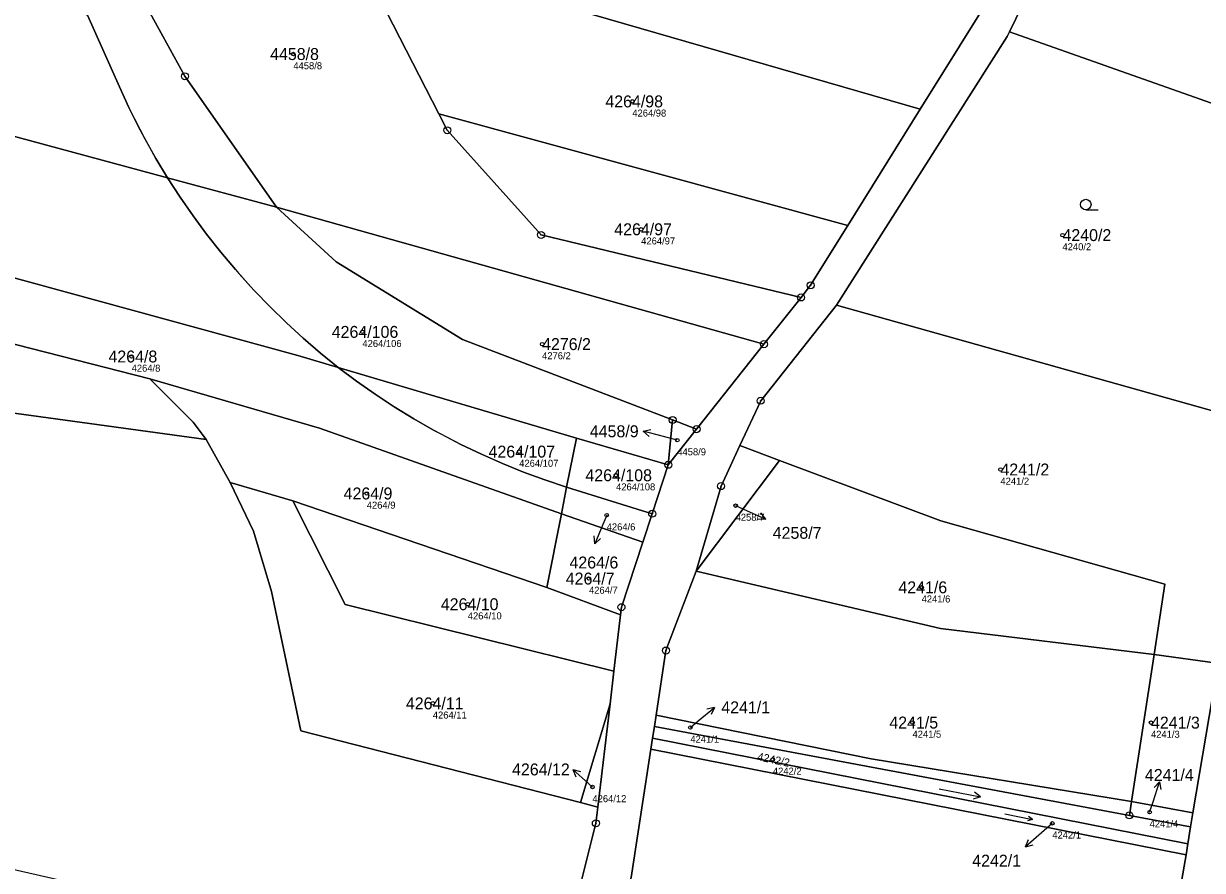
# Model space of a CAD drawing. Extents: x -739214 to -733252, y -1147612 to -1142842.
# Drawn here: x -736907.7 to -736739.7, y -1146244.9 to -1146124.1 of the extents above; entities that cross this region are included whole.
import ezdxf

# ---------------------------------------------------------------- set-up
doc = ezdxf.new("R2010")
doc.units = 0
for name, color, linetype in [('Definiční body', 7, 'Continuous'), ('Hranice parcel', 7, 'Continuous'), ('Parcelní čísla', 7, 'Continuous'), ('Polygon parcely', 7, 'Continuous'), ('Pop  PČ popisy', 7, 'Continuous'), ('Značky bodu BP', 7, 'Continuous'), ('Značky kultur', 7, 'Continuous')]:
    doc.layers.add(name, color=color, linetype=linetype)

msp = doc.modelspace()

# ---------------------------------------------------------------- linework, layer by layer
at = {"layer": 'Definiční body'}
for centre in [(-736869.24, -1146128.5), (-736820.95, -1146135.25), (-736819.68, -1146153.48), (-736759.66, -1146154.31), (-736859.4, -1146168.11), (-736833.8, -1146169.85), (-736892.28, -1146171.62), (-736814.54, -1146183.55), (-736837.06, -1146185.18), (-736823.26, -1146188.55), (-736768.5, -1146187.73), (-736858.78, -1146191.15), (-736824.6, -1146194.25), (-736806.23, -1146192.88), (-736827.12, -1146203.28), (-736779.73, -1146204.53), (-736844.39, -1146206.94), (-736849.37, -1146221.08), (-736781.03, -1146223.81), (-736747.05, -1146223.82), (-736812.68, -1146224.52), (-736800.92, -1146229.07), (-736826.63, -1146233), (-736747.25, -1146236.58), (-736761.11, -1146238.18)]:
    msp.add_circle(centre, 0.25, dxfattribs=at)
at = {"layer": 'Hranice parcel'}
for p, q in [((-736768.72, -1146118.36), (-736779.92, -1146136.37)), ((-736894.03, -1146133.17), (-736898.55, -1146122.95)), ((-736767.21, -1146125.35), (-736726.44, -1146139.74)), ((-736884.69, -1146131.66), (-736871.63, -1146150.35)), ((-736929.53, -1146134.68), (-736887.15, -1146146.15)), ((-736779.92, -1146136.37), (-736790.23, -1146152.94)), ((-736847.31, -1146139.36), (-736848.52, -1146137)), ((-736790.23, -1146152.94), (-736848.52, -1146137)), ((-736871.63, -1146150.35), (-736887.15, -1146146.15)), ((-736949, -1146149.47), (-736868.58, -1146171.48)), ((-736871.63, -1146150.35), (-736802.19, -1146169.86)), ((-736790.23, -1146152.94), (-736795.54, -1146161.47)), ((-736951.05, -1146159.13), (-736889.7, -1146174.8)), ((-736795.54, -1146161.47), (-736796.91, -1146163.2)), ((-736802.19, -1146169.86), (-736796.91, -1146163.2)), ((-736733.19, -1146180.81), (-736791.88, -1146164.3)), ((-736811.79, -1146181.98), (-736802.19, -1146169.86)), ((-736868.58, -1146171.48), (-736862.84, -1146173.19)), ((-736862.84, -1146173.19), (-736828.92, -1146183.27)), ((-736815.2, -1146180.67), (-736815.82, -1146187.06)), ((-736815.82, -1146187.06), (-736811.79, -1146181.98)), ((-736811.79, -1146181.98), (-736815.2, -1146180.67)), ((-736881.65, -1146183.43), (-736878.24, -1146189.59)), ((-736828.92, -1146183.27), (-736830.31, -1146190.25)), ((-736828.92, -1146183.27), (-736815.82, -1146187.06)), ((-736805.62, -1146184.32), (-736799.97, -1146186.44)), ((-736815.82, -1146187.06), (-736818.11, -1146194.04)), ((-736811.83, -1146202.22), (-736799.97, -1146186.44)), ((-736878.24, -1146189.59), (-736869.32, -1146192.22)), ((-736830.31, -1146190.25), (-736831.06, -1146194.05)), ((-736818.11, -1146194.04), (-736830.31, -1146190.25)), ((-736869.32, -1146192.22), (-736833.14, -1146204.56)), ((-736831.06, -1146194.05), (-736833.14, -1146204.56)), ((-736831.06, -1146194.05), (-736819.44, -1146198.08)), ((-736818.11, -1146194.04), (-736819.44, -1146198.08)), ((-736833.14, -1146204.56), (-736822.62, -1146208.45)), ((-736822.62, -1146208.45), (-736823.57, -1146216.47)), ((-736746.61, -1146214.12), (-736749.83, -1146235.07)), ((-736746.61, -1146214.12), (-736737.62, -1146215.32)), ((-736823.57, -1146216.47), (-736824.12, -1146221.12)), ((-736828.32, -1146235.2), (-736824.12, -1146221.12)), ((-736824.12, -1146221.12), (-736825.87, -1146235.87)), ((-736817.56, -1146222.75), (-736817.81, -1146224.36)), ((-736817.81, -1146224.36), (-736818.08, -1146226.04)), ((-736817.81, -1146224.36), (-736750.13, -1146237.05)), ((-736818.08, -1146226.04), (-736818.33, -1146227.6)), ((-736818.33, -1146227.6), (-736742.05, -1146242.68)), ((-736741.8, -1146241.12), (-736818.08, -1146226.04)), ((-736828.32, -1146235.2), (-736825.87, -1146235.87)), ((-736750.13, -1146237.05), (-736749.83, -1146235.07)), ((-736749.83, -1146235.07), (-736741.07, -1146236.7)), ((-736750.13, -1146237.05), (-736741.41, -1146238.68)), ((-736741.41, -1146238.68), (-736741.07, -1146236.7)), ((-736741.41, -1146238.68), (-736741.8, -1146241.12)), ((-736741.8, -1146241.12), (-736742.05, -1146242.68))]:
    msp.add_line(p, q, dxfattribs=at)
for points in [[(-736711.04, -1146011.3), (-736716.18, -1146010.57), (-736725.41, -1146029.07), (-736733.92, -1146047.65), (-736741.44, -1146068.31), (-736754.37, -1146098.97), (-736767.21, -1146125.35)], [(-736902.13, -1146082.77), (-736901.23, -1146090.61), (-736897.28, -1146103.58), (-736893.8, -1146115.01), (-736887.82, -1146125.93), (-736884.69, -1146131.66)], [(-736848.52, -1146137), (-736858.72, -1146117.04), (-736859.58, -1146114.05)], [(-736859.58, -1146114.05), (-736835.36, -1146120.3), (-736779.92, -1146136.37)], [(-736767.21, -1146125.35), (-736767.52, -1146125.99), (-736791.88, -1146164.3)], [(-736887.15, -1146146.15), (-736888.82, -1146143.39), (-736889.7, -1146141.83), (-736891.24, -1146138.99), (-736892.68, -1146136.1), (-736894.03, -1146133.17)], [(-736796.91, -1146163.2), (-736833.94, -1146154.29), (-736847.31, -1146139.36)], [(-736862.84, -1146173.19), (-736865.37, -1146171.14), (-736867.83, -1146169.02), (-736870.22, -1146166.82), (-736872.55, -1146164.55), (-736874.8, -1146162.21), (-736875.34, -1146161.64), (-736877.5, -1146159.21), (-736879.59, -1146156.72), (-736881.6, -1146154.17), (-736883.53, -1146151.55), (-736885.38, -1146148.88), (-736887.15, -1146146.15)], [(-736815.2, -1146180.67), (-736845.12, -1146169.19), (-736863.15, -1146158.13), (-736871.63, -1146150.35)], [(-736881.65, -1146183.43), (-736910.07, -1146179.55), (-736947.77, -1146171.35), (-736994.32, -1146155.97), (-737003.53, -1146154.25), (-737005.4, -1146157.41)], [(-736791.88, -1146164.3), (-736802.66, -1146177.93), (-736805.62, -1146184.32)], [(-736830.31, -1146190.25), (-736833.39, -1146189.22), (-736836.44, -1146188.09), (-736839.45, -1146186.87), (-736842.43, -1146185.55), (-736845.36, -1146184.15), (-736846.39, -1146183.62), (-736849.26, -1146182.1), (-736852.09, -1146180.49), (-736854.86, -1146178.79), (-736857.58, -1146177), (-736860.24, -1146175.14), (-736862.84, -1146173.19)], [(-736889.7, -1146174.8), (-736865.53, -1146181.85), (-736831.06, -1146194.05)], [(-736889.7, -1146174.8), (-736883.52, -1146180.99), (-736881.65, -1146183.43)], [(-736805.62, -1146184.32), (-736808.3, -1146190.1), (-736811.83, -1146202.22)], [(-736799.97, -1146186.44), (-736777.01, -1146195.04), (-736745.07, -1146204.08), (-736746.61, -1146214.12)], [(-736878.24, -1146189.59), (-736874.93, -1146196.5), (-736872.34, -1146205.13), (-736868.17, -1146224.99), (-736828.32, -1146235.2)], [(-736869.32, -1146192.22), (-736861.84, -1146207), (-736823.57, -1146216.47)], [(-736819.44, -1146198.08), (-736822.49, -1146207.36), (-736822.62, -1146208.45)], [(-736811.83, -1146202.22), (-736816.15, -1146213.54), (-736817.56, -1146222.75)], [(-736746.61, -1146214.12), (-736777.03, -1146210.39), (-736811.83, -1146202.22)], [(-736741.07, -1146236.7), (-736738.27, -1146220.16), (-736737.62, -1146215.32)], [(-736749.83, -1146235.07), (-736786.91, -1146228.96), (-736817.56, -1146222.75)], [(-736818.33, -1146227.6), (-736821.12, -1146245.91), (-736826.96, -1146267.27), (-736832.53, -1146282.89)], [(-736825.87, -1146235.87), (-736826.14, -1146238.17), (-736833.12, -1146266.08)], [(-736742.05, -1146242.68), (-736743.41, -1146250.51), (-736741.88, -1146280.01), (-736741.22, -1146298.2)]]:
    msp.add_lwpolyline(points, dxfattribs=at)
at = {"layer": 'Polygon parcely'}
for points in [[(-736724.22, -1146126.64), (-736721.15, -1146114.73), (-736719.03, -1146108.98), (-736713.68, -1146094.58), (-736709.82, -1146079.79), (-736706.67, -1146043.66), (-736707.02, -1146038.42), (-736707.22, -1146035.46), (-736710.43, -1146014.29), (-736711.04, -1146011.3), (-736716.18, -1146010.57), (-736725.41, -1146029.07), (-736733.92, -1146047.65), (-736741.44, -1146068.31), (-736754.37, -1146098.97), (-736767.21, -1146125.35), (-736726.44, -1146139.74)], [(-736897.28, -1146103.58), (-736893.8, -1146115.01), (-736887.82, -1146125.93), (-736884.69, -1146131.66), (-736871.63, -1146150.35), (-736802.19, -1146169.86), (-736796.91, -1146163.2), (-736833.94, -1146154.29), (-736847.31, -1146139.36), (-736848.52, -1146137), (-736858.72, -1146117.04), (-736859.58, -1146114.05), (-736864.83, -1146095.86), (-736864.48, -1146089.43), (-736902.13, -1146082.77), (-736901.23, -1146090.61)], [(-736835.36, -1146120.3), (-736779.92, -1146136.37), (-736768.72, -1146118.36), (-736798.7, -1146107.53), (-736847.61, -1146092.42), (-736864.48, -1146089.43), (-736864.83, -1146095.86), (-736859.58, -1146114.05)], [(-736983.7, -1146103.21), (-737008.18, -1146111.58), (-736991.48, -1146116.71), (-736929.53, -1146134.68), (-736887.15, -1146146.15), (-736888.82, -1146143.39), (-736889.7, -1146141.83), (-736891.24, -1146138.99), (-736892.68, -1146136.1), (-736894.03, -1146133.17), (-736898.55, -1146122.95), (-736977.4, -1146101.1)], [(-736949, -1146149.47), (-736868.58, -1146171.48), (-736862.84, -1146173.19), (-736865.37, -1146171.14), (-736867.83, -1146169.02), (-736870.22, -1146166.82), (-736872.55, -1146164.55), (-736874.8, -1146162.21), (-736875.34, -1146161.64), (-736877.5, -1146159.21), (-736879.59, -1146156.72), (-736881.6, -1146154.17), (-736883.53, -1146151.55), (-736885.38, -1146148.88), (-736887.15, -1146146.15), (-736929.53, -1146134.68), (-736991.48, -1146116.71), (-737008.18, -1146111.58), (-737043.27, -1146123.57), (-737022.12, -1146129.78), (-736982.56, -1146139.99)], [(-736859.58, -1146114.05), (-736858.72, -1146117.04), (-736848.52, -1146137), (-736790.23, -1146152.94), (-736779.92, -1146136.37), (-736835.36, -1146120.3)], [(-736733.19, -1146180.81), (-736726.44, -1146139.74), (-736767.21, -1146125.35), (-736767.52, -1146125.99), (-736791.88, -1146164.3)], [(-737005.4, -1146157.41), (-737003.53, -1146154.25), (-736994.32, -1146155.97), (-736947.77, -1146171.35), (-736910.07, -1146179.55), (-736881.65, -1146183.43), (-736883.52, -1146180.99), (-736889.7, -1146174.8), (-736951.05, -1146159.13), (-737006.3, -1146146.61), (-737061.97, -1146129.96), (-737079.85, -1146136.07)], [(-736848.52, -1146137), (-736847.31, -1146139.36), (-736833.94, -1146154.29), (-736796.91, -1146163.2), (-736795.54, -1146161.47), (-736790.23, -1146152.94)], [(-736863.15, -1146158.13), (-736871.63, -1146150.35), (-736887.15, -1146146.15), (-736885.38, -1146148.88), (-736883.53, -1146151.55), (-736881.6, -1146154.17), (-736879.59, -1146156.72), (-736877.5, -1146159.21), (-736876.99, -1146159.8), (-736874.8, -1146162.21), (-736872.55, -1146164.55), (-736870.22, -1146166.82), (-736867.83, -1146169.02), (-736865.37, -1146171.14), (-736862.84, -1146173.19), (-736828.92, -1146183.27), (-736815.82, -1146187.06), (-736815.2, -1146180.67), (-736845.12, -1146169.19)], [(-736830.31, -1146190.25), (-736833.39, -1146189.22), (-736836.44, -1146188.09), (-736839.45, -1146186.87), (-736842.43, -1146185.55), (-736845.36, -1146184.15), (-736846.39, -1146183.62), (-736849.26, -1146182.1), (-736852.09, -1146180.49), (-736854.86, -1146178.79), (-736857.58, -1146177), (-736860.24, -1146175.14), (-736862.84, -1146173.19), (-736868.58, -1146171.48), (-736949, -1146149.47), (-736951.05, -1146159.13), (-736889.7, -1146174.8), (-736865.53, -1146181.85), (-736831.06, -1146194.05)], [(-736815.2, -1146180.67), (-736811.79, -1146181.98), (-736802.19, -1146169.86), (-736871.63, -1146150.35), (-736863.15, -1146158.13), (-736845.12, -1146169.19)], [(-737021.63, -1146188.99), (-737023.93, -1146188.41), (-737031.55, -1146214.89), (-736983.7, -1146228.83), (-736939.24, -1146237.89), (-736893.84, -1146248.24), (-736833.12, -1146266.08), (-736826.14, -1146238.17), (-736825.87, -1146235.87), (-736828.32, -1146235.2), (-736868.17, -1146224.99), (-736872.34, -1146205.13), (-736874.93, -1146196.5), (-736878.24, -1146189.59), (-736881.65, -1146183.43), (-736910.07, -1146179.55), (-736947.77, -1146171.35), (-736994.32, -1146155.97), (-737003.53, -1146154.25), (-737005.4, -1146157.41), (-737011.85, -1146169.96)], [(-736746.61, -1146214.12), (-736737.62, -1146215.32), (-736733.19, -1146180.81), (-736791.88, -1146164.3), (-736802.66, -1146177.93), (-736805.62, -1146184.32), (-736799.97, -1146186.44), (-736777.01, -1146195.04), (-736745.07, -1146204.08)], [(-736862.84, -1146173.19), (-736860.24, -1146175.14), (-736857.58, -1146177), (-736854.86, -1146178.79), (-736852.09, -1146180.49), (-736849.26, -1146182.1), (-736848.25, -1146182.65), (-736845.36, -1146184.15), (-736842.43, -1146185.55), (-736839.45, -1146186.87), (-736836.44, -1146188.09), (-736833.39, -1146189.22), (-736830.31, -1146190.25), (-736828.92, -1146183.27)], [(-736878.24, -1146189.59), (-736869.32, -1146192.22), (-736833.14, -1146204.56), (-736831.06, -1146194.05), (-736865.53, -1146181.85), (-736889.7, -1146174.8), (-736883.52, -1146180.99), (-736881.65, -1146183.43)], [(-736815.82, -1146187.06), (-736811.79, -1146181.98), (-736815.2, -1146180.67)], [(-736830.31, -1146190.25), (-736818.11, -1146194.04), (-736815.82, -1146187.06), (-736828.92, -1146183.27)], [(-736811.83, -1146202.22), (-736799.97, -1146186.44), (-736805.62, -1146184.32), (-736808.3, -1146190.1)], [(-736746.61, -1146214.12), (-736745.07, -1146204.08), (-736777.01, -1146195.04), (-736799.97, -1146186.44), (-736811.83, -1146202.22), (-736777.03, -1146210.39)], [(-736868.17, -1146224.99), (-736828.32, -1146235.2), (-736824.12, -1146221.12), (-736823.57, -1146216.47), (-736861.84, -1146207), (-736869.32, -1146192.22), (-736878.24, -1146189.59), (-736874.93, -1146196.5), (-736872.34, -1146205.13)], [(-736818.11, -1146194.04), (-736830.31, -1146190.25), (-736831.06, -1146194.05), (-736819.44, -1146198.08)], [(-736861.84, -1146207), (-736823.57, -1146216.47), (-736822.62, -1146208.45), (-736833.14, -1146204.56), (-736869.32, -1146192.22)], [(-736833.14, -1146204.56), (-736822.62, -1146208.45), (-736822.49, -1146207.36), (-736819.44, -1146198.08), (-736831.06, -1146194.05)], [(-736817.56, -1146222.75), (-736786.91, -1146228.96), (-736749.83, -1146235.07), (-736746.61, -1146214.12), (-736777.03, -1146210.39), (-736811.83, -1146202.22), (-736816.15, -1146213.54)], [(-736738.27, -1146220.16), (-736737.62, -1146215.32), (-736746.61, -1146214.12), (-736749.83, -1146235.07), (-736741.07, -1146236.7)], [(-736825.87, -1146235.87), (-736824.12, -1146221.12), (-736828.32, -1146235.2)], [(-736786.91, -1146228.96), (-736817.56, -1146222.75), (-736817.81, -1146224.36), (-736750.13, -1146237.05), (-736749.83, -1146235.07)], [(-736818.08, -1146226.04), (-736741.8, -1146241.12), (-736741.41, -1146238.68), (-736750.13, -1146237.05), (-736817.81, -1146224.36)], [(-736821.12, -1146245.91), (-736826.96, -1146267.27), (-736832.53, -1146282.89), (-736806.23, -1146290.17), (-736762.93, -1146295.92), (-736741.22, -1146298.2), (-736741.88, -1146280.01), (-736743.41, -1146250.51), (-736742.05, -1146242.68), (-736818.33, -1146227.6)], [(-736742.05, -1146242.68), (-736741.8, -1146241.12), (-736818.08, -1146226.04), (-736818.33, -1146227.6)], [(-736750.13, -1146237.05), (-736741.41, -1146238.68), (-736741.07, -1146236.7), (-736749.83, -1146235.07)]]:
    msp.add_lwpolyline(points, close=True, dxfattribs=at)
for points in [[(-736733.16, -1146033.16), (-736740.22, -1146051.47), (-736745.33, -1146066.4), (-736751.96, -1146080.47), (-736755.93, -1146091.93), (-736756.37, -1146093.19), (-736759.66, -1146099.89), (-736768.72, -1146118.36), (-736779.92, -1146136.37), (-736790.23, -1146152.94), (-736795.54, -1146161.47), (-736796.91, -1146163.2), (-736802.19, -1146169.86), (-736811.79, -1146181.98), (-736815.82, -1146187.06)], [(-736845.18, -1146312.06), (-736838.23, -1146298.86), (-736832.53, -1146282.89), (-736826.96, -1146267.27), (-736821.12, -1146245.91), (-736818.33, -1146227.6), (-736818.08, -1146226.04), (-736817.81, -1146224.36), (-736817.56, -1146222.75), (-736816.15, -1146213.54), (-736811.83, -1146202.22), (-736808.3, -1146190.1), (-736805.62, -1146184.32), (-736802.66, -1146177.93), (-736791.88, -1146164.3), (-736767.52, -1146125.99), (-736767.21, -1146125.35), (-736754.37, -1146098.97), (-736741.44, -1146068.31), (-736733.92, -1146047.65)], [(-736908.12, -1146103.74), (-736907.66, -1146104.35), (-736906.57, -1146105.93), (-736905.56, -1146107.57), (-736904.64, -1146109.25), (-736903.81, -1146110.98), (-736903.07, -1146112.75), (-736898.55, -1146122.95), (-736894.03, -1146133.17), (-736892.68, -1146136.1), (-736891.89, -1146137.71), (-736890.4, -1146140.57), (-736888.82, -1146143.39), (-736887.15, -1146146.15), (-736871.63, -1146150.35), (-736884.69, -1146131.66), (-736887.82, -1146125.93), (-736893.8, -1146115.01), (-736897.28, -1146103.58), (-736901.23, -1146090.61), (-736902.13, -1146082.77), (-736911.87, -1146081.05)], [(-736815.82, -1146187.06), (-736818.11, -1146194.04), (-736819.44, -1146198.08), (-736822.49, -1146207.36), (-736822.62, -1146208.45), (-736823.57, -1146216.47), (-736824.12, -1146221.12), (-736825.87, -1146235.87), (-736826.14, -1146238.17), (-736833.12, -1146266.08), (-736833.26, -1146266.65), (-736844.06, -1146297.34), (-736846.68, -1146304.78), (-736861.12, -1146328.89)], [(-736738.27, -1146220.16), (-736741.07, -1146236.7), (-736741.41, -1146238.68), (-736741.8, -1146241.12), (-736742.05, -1146242.68), (-736743.41, -1146250.51)]]:
    msp.add_lwpolyline(points, dxfattribs=at)
at = {"layer": 'Pop  PČ popisy'}
for p, q in [((-736819.39, -1146182.26), (-736818.29, -1146182.04)), ((-736816.49, -1146183.04), (-736819.39, -1146182.26)), ((-736819.39, -1146182.26), (-736818.55, -1146183.01)), ((-736814.54, -1146183.55), (-736816.49, -1146183.04)), ((-736806.23, -1146192.88), (-736804.68, -1146193.57)), ((-736804.68, -1146193.57), (-736801.94, -1146194.79)), ((-736801.94, -1146194.79), (-736802.65, -1146193.93)), ((-736825.14, -1146195.55), (-736826.31, -1146198.31)), ((-736824.6, -1146194.25), (-736825.14, -1146195.55)), ((-736801.94, -1146194.79), (-736803.06, -1146194.84)), ((-736826.31, -1146198.31), (-736826.38, -1146197.2)), ((-736826.31, -1146198.31), (-736825.46, -1146197.59)), ((-736811.56, -1146223.58), (-736809.26, -1146221.65)), ((-736809.26, -1146221.65), (-736810.35, -1146221.91)), ((-736809.26, -1146221.65), (-736809.71, -1146222.68)), ((-736812.68, -1146224.52), (-736811.56, -1146223.58)), ((-736827.18, -1146232.5), (-736829.41, -1146230.49)), ((-736829.41, -1146230.49), (-736828.33, -1146230.79)), ((-736829.41, -1146230.49), (-736829, -1146231.53)), ((-736826.63, -1146233), (-736827.18, -1146232.5)), ((-736746.76, -1146235.11), (-736745.83, -1146232.26)), ((-736745.83, -1146232.26), (-736746.62, -1146233.05)), ((-736745.83, -1146232.26), (-736745.67, -1146233.36)), ((-736747.25, -1146236.58), (-736746.76, -1146235.11)), ((-736761.11, -1146238.18), (-736762.66, -1146239.54)), ((-736762.66, -1146239.54), (-736764.93, -1146241.51)), ((-736764.93, -1146241.51), (-736764.5, -1146240.47)), ((-736764.93, -1146241.51), (-736763.84, -1146241.23))]:
    msp.add_line(p, q, dxfattribs=at)
at = {"layer": 'Značky bodu BP'}
for centre, radius in [((-736884.69, -1146131.66), 0.5), ((-736884.69, -1146131.66), 0.0303), ((-736847.31, -1146139.36), 0.5), ((-736847.31, -1146139.36), 0.0303), ((-736833.94, -1146154.29), 0.5), ((-736833.94, -1146154.29), 0.0303), ((-736795.54, -1146161.47), 0.5), ((-736795.54, -1146161.47), 0.0303), ((-736796.91, -1146163.2), 0.5), ((-736796.91, -1146163.2), 0.0303), ((-736802.19, -1146169.86), 0.5), ((-736802.19, -1146169.86), 0.0303), ((-736802.66, -1146177.93), 0.5), ((-736802.66, -1146177.93), 0.0303), ((-736815.2, -1146180.67), 0.5), ((-736815.2, -1146180.67), 0.0303), ((-736811.79, -1146181.98), 0.5), ((-736811.79, -1146181.98), 0.0303), ((-736815.82, -1146187.06), 0.5), ((-736815.82, -1146187.06), 0.0303), ((-736808.3, -1146190.1), 0.5), ((-736808.3, -1146190.1), 0.0303), ((-736818.11, -1146194.04), 0.5), ((-736818.11, -1146194.04), 0.0303), ((-736822.49, -1146207.36), 0.5), ((-736822.49, -1146207.36), 0.0303), ((-736816.15, -1146213.54), 0.5), ((-736816.15, -1146213.54), 0.0303), ((-736826.14, -1146238.17), 0.5), ((-736750.13, -1146237.05), 0.5), ((-736750.13, -1146237.05), 0.0303), ((-736826.14, -1146238.17), 0.0303)]:
    msp.add_circle(centre, radius, dxfattribs=at)
at = {"layer": 'Značky kultur'}
for p, q in [((-736756.34, -1146150.71), (-736754.59, -1146150.71)), ((-736777.22, -1146233.27), (-736771.33, -1146234.41)), ((-736771.33, -1146234.41), (-736772.19, -1146233.74)), ((-736771.33, -1146234.41), (-736772.39, -1146234.72)), ((-736767.89, -1146236.81), (-736763.95, -1146237.65)), ((-736763.95, -1146237.65), (-736764.66, -1146237.84)), ((-736763.95, -1146237.65), (-736764.52, -1146237.18))]:
    msp.add_line(p, q, dxfattribs=at)
msp.add_circle((-736756.34, -1146149.96), 0.75, dxfattribs=at)

# ---------------------------------------------------------------- texts
at = {"layer": 'Definiční body'}
for s, p in [('4458/8', (-736869.24, -1146130.66)), ('4264/98', (-736820.95, -1146137.41)), ('4264/97', (-736819.68, -1146155.64)), ('4240/2', (-736759.66, -1146156.47)), ('4264/106', (-736859.4, -1146170.27)), ('4276/2', (-736833.8, -1146172.01)), ('4264/8', (-736892.28, -1146173.78)), ('4458/9', (-736814.54, -1146185.71)), ('4264/107', (-736837.06, -1146187.34)), ('4241/2', (-736768.5, -1146189.89)), ('4264/108', (-736823.26, -1146190.71)), ('4264/9', (-736858.78, -1146193.31)), ('4258/7', (-736806.23, -1146195.04)), ('4264/6', (-736824.6, -1146196.41)), ('4264/7', (-736827.12, -1146205.44)), ('4241/6', (-736779.73, -1146206.69)), ('4264/10', (-736844.39, -1146209.1)), ('4264/11', (-736849.37, -1146223.24)), ('4241/1', (-736812.68, -1146226.68)), ('4241/5', (-736781.03, -1146225.97)), ('4241/3', (-736747.05, -1146225.98)), ('4242/2', (-736800.92, -1146231.23)), ('4264/12', (-736826.63, -1146235.16)), ('4242/1', (-736761.11, -1146240.34)), ('4241/4', (-736747.25, -1146238.74))]:
    msp.add_text(s, height=1, dxfattribs=at).set_placement(p)
at = {"layer": 'Parcelní čísla'}
for s, p in [('4458/8', (-736872.55, -1146129.35)), ('4264/98', (-736824.79, -1146136.1)), ('4264/97', (-736823.52, -1146154.33)), ('4240/2', (-736759.66, -1146155.16)), ('4264/106', (-736863.77, -1146168.96)), ('4276/2', (-736833.8, -1146170.7)), ('4264/8', (-736895.58, -1146172.47)), ('4458/9', (-736827, -1146183.13)), ('4264/107', (-736841.43, -1146186.03)), ('4241/2', (-736768.5, -1146188.58)), ('4264/108', (-736827.63, -1146189.4)), ('4264/9', (-736862.08, -1146192)), ('4258/7', (-736800.94, -1146197.61)), ('4264/6', (-736829.9, -1146201.84)), ('4264/7', (-736830.43, -1146204.13)), ('4241/6', (-736783.04, -1146205.38)), ('4264/10', (-736848.23, -1146207.79)), ('4264/11', (-736853.21, -1146221.93)), ('4241/1', (-736808.27, -1146222.49)), ('4241/5', (-736784.33, -1146224.66)), ('4241/3', (-736747.05, -1146224.67)), ('4264/12', (-736838.08, -1146231.34)), ('4241/4', (-736747.92, -1146232.13)), ('4242/1', (-736772.52, -1146244.35))]:
    msp.add_text(s, height=1.7, dxfattribs=at).set_placement(p)
msp.add_text('4242/2', height=1.14, rotation=348, dxfattribs=at).set_placement((-736803.21, -1146229.17))

doc.saveas('drawing.dxf')
